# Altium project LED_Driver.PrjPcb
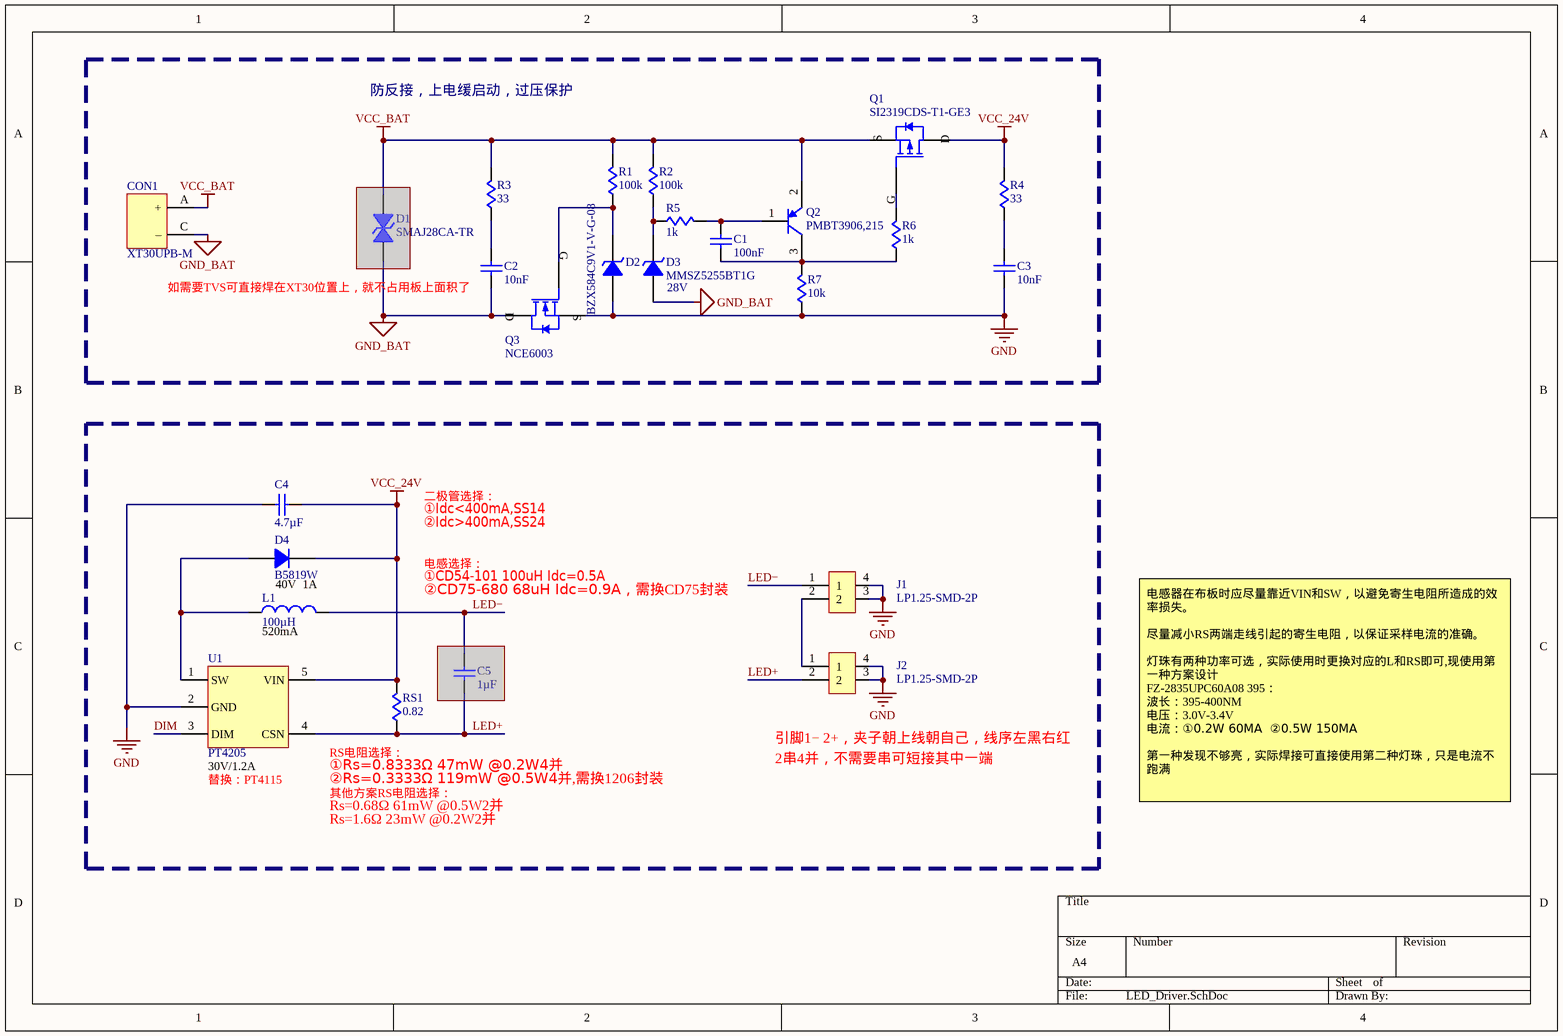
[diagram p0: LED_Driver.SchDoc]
1 sheet, 25 parts. Net scope: global (net labels, ports and power ports of the same name join across sheets).
Board file: LED_Driver.PcbDoc

## Sheet LED_Driver.SchDoc
size A4; SheetNumber: 1; SheetTotal: 1

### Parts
C1  value 100nF  [C 0603(1608)100_L]  (hidden comment: CL10B104KB8NNNC)
C2  value 10nF  [C 0603(1608)100_L]  (hidden comment: CL10B103KB8NNNC)
C3  value 10nF  [C 0603(1608)100_L]  (hidden comment: CL10B103KB8NNNC)
C4  value 4.7µF  [C 0805(2012)_L]  (hidden comment: CL21A475KBQNNNE)
C5  value 1µF  [C 0603(1608)100_L]  (hidden comment: CL10A105KB8NNNC)  (masked out: inside a compile mask, not in the netlist)
CON1  XT30UPB-M  [XT30UPB-M-内嵌（翻转）]
D1  SMAJ28CA-TR  [DO-214AC(SMA)-AA]  (masked out: inside a compile mask, not in the netlist)
D2  BZX584C9V1-V-G-08  [SOD-523]
D3  MMSZ5255BT1G  Voltage Rating (DC): 28V  [SOD-123]
D4  B5819W  Forward Current: 1A  Reverse Voltage (DC): 40V  [SOD-123]
J1  LP1.25-SMD-2P  [GH1.25-WS-2P]
J2  LP1.25-SMD-2P  [GH1.25-WS-2P]
L1  value 100µH  Current Rating: 520mA  [CD54]  (hidden comment: CD54NP-101KC)
Q1  SI2319CDS-T1-GE3  [SOT23-3L]
Q2  PMBT3906,215  [SOT23-3L]
Q3  NCE6003  [SOT23-3L]
R1  value 100k  [R 0603(1608)_L]  (hidden comment: RC0603FR-07100KL)
R2  value 100k  [R 0603(1608)_L]  (hidden comment: RC0603FR-07100KL)
R3  value 33  [R 0603(1608)_L]  (hidden comment: RC0603FR-0733RL)
R4  value 33  [R 0603(1608)_L]  (hidden comment: RC0603FR-0733RL)
R5  value 1k  [R 0603(1608)_L]  (hidden comment: RC0603FR-071KL)
R6  value 1k  [R 0603(1608)_L]  (hidden comment: RC0603FR-071KL)
R7  value 10k  [R 0603(1608)_L]  (hidden comment: RC0603FR-0710KL)
RS1  value 0.82  [R 0603(1608)_L]  (hidden comment: 0603WAF820LT5E)
U1  PT4205  [SOT89-5N]

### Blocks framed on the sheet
防反接，上电缓启动，过压保护: C1-C3 CON1 D1-D3 Q1-Q3 R1-R7

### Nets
GND: C3.1 C4.1 D2.1(A) J1.3 J1.4 J2.3 J2.4 Q3.2(SOURCE) R7.1 U1.2(GND)
GND_BAT: C2.1 CON1.C(–) D3.1(A) Q3.3(DRAIN)
VCC_24V: C4.2 D4.2(K) Q1.3(DRAIN) R4.2 RS1.2 U1.5(VIN)
VCC_BAT: CON1.A(+) Q1.2(SOURCE) Q2.2(E) R1.2 R2.2 R3.2
DIM: U1.3(DIM)
LED+: J2.2 RS1.1 U1.4(CSN)
LED−: J1.1 L1.2
NetC1_1: C1.1 Q2.3(C) R6.1 R7.2
NetC1_2: C1.2 Q2.1(B) R5.2
NetC2_2: C2.2 R3.1
NetC3_2: C3.2 R4.1
NetD2_2: D2.2(K) Q3.1(GATE) R1.1
NetD3_2: D3.2(K) R2.1 R5.1
NetD4_1: D4.1(A) L1.1 U1.1(SW)
NetJ1_2: J1.2 J2.1
NetQ1_1: Q1.1(GATE) R6.2

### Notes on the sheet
- 如需要TVS可直接焊在XT30位置上，就不占用板上面积了
- ①Idc<400mA,SS14
- 二极管选择：
- ①CD54-101 100uH Idc=0.5A
- ②Idc>400mA,SS24
- 电感选择：
- ②CD75-680 68uH Idc=0.9A，需换CD75封装
- (near U1) 30V/1.2A
- (near U1) 替换：PT4115
- ①Rs=0.8333Ω 47mW @0.2W4并
- ②Rs=0.3333Ω 119mW @0.5W4并,需换1206封装
- RS电阻选择：
- (near J2) 引脚1− 2+，夹子朝上线朝自己，线序左黑右红
- 2串4并，不需要串可短接其中一端
- Rs=0.68Ω 61mW @0.5W2并
- Rs=1.6Ω 23mW @0.2W2并
- 其他方案RS电阻选择：
- 电感器在布板时应尽量靠近VIN和SW，以避免寄生电阻所造成的效率损失。
  尽量减小RS两端走线引起的寄生电阻，以保证采样电流的准确。
  灯珠有两种功率可选，实际使用时更换对应的L和RS即可,现使用第一种方案设计
  FZ-2835UPC60A08 395：
  波长：395-400NM
  电压：3.0V-3.4V
  电流：①0.2W 60MA  ②0.5W 150MA
  第一种发现不够亮，实际焊接可直接使用第二种灯珠，只是电流不跑满

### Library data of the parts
C1 = CMP-001-00085-4: Multi Layer Ceramic Capacitor (MLCC) / Cap Ceramic 0.1uF 50V X7R 10% Pad SMD 0603 125¡ãC T/R
C2 C3 = CMP-001-00105-3: CAP CER 10000PF 50V X7R 0603; Material: Ceramic; Tolerance: 10%
C4 = CMP-001-00100-4: CAP CER 4.7UF 50V X5R 0805; Tolerance: 10%
C5 = CMP-001-00101-3: Ceramic capacitor SMD-0603 1000nF/50V X5R# K +-10%, Samsung, RoHS; Dielectric: X5R; Voltage Rating: 50V; Tolerance: 10%
CON1 = CMP-002-00073-11: 12.7x10.2mm 铜镀金 DC500V 15A; Momentary Current: 30A; Voltage Rating: 500V
D1 = CMP-004-00058-1: SMAJ Series 400 W 32.7 V Bi Directional Surface Mount TVS Diode - DO-214AC; Operating Supply Voltage: 28V; Clamping Voltage-Max: 59V; Test Current: 1mA; Power Dissipation: 400W; Element Configuration: Single; Max Reverse Leakage Current: 200nA; Reverse Breakdown Voltage: 31.1V; Max Breakdown Voltage: 32.7V; Value: 510pF; Peak Pulse Current: 39A; Number of Bidirectional Channels: 1; ESD Protection: Yes; Power Line Protection: No; Diode Type: ZENER
D2 = CMP-004-00055-5: Diode Zener Single 9.1V 5% 200mW 2-Pin SOD-523 T/R; Impedance: 15R; ESD Protection: No; Test Current: 5mA; Max Reverse Leakage Current: 500nA
D3 = CMP-004-00057-2: MMSZ5255BT1 Series 500 mW 10 mA 28 V SMT Zener Voltage Regulator - SOD-123; Max Reverse Current: 100nA; Voltage Tolerance: 5%; Power Rating: 500mW; Element Configuration: Single; Forward Voltage: 900mV; ESD Protection: Yes; Test Current: 4.5mA; Impedance: 44R; Material: Plastic; Zener Current: 10mA
D4 = CMP-004-00044-11: DIODE SCHOTTKY 20V 1A SOD123; Max Forward Surge Current (Ifsm): 10A; Forward Voltage: 550mV; Max Power Dissipation: 250mW; Element Configuration: Single; Max Reverse Current: 1mA
J1 J2 = CMP-002-00326-2: 脚距1.25，表面贴装，2pin接插件
L1 = CMP-006-00038-2: Ind Power Unshielded Wirewound 100uH 10% 1KHz 520mA Carrier T/R; Core Material: Ferrite; DC Resistance (DCR): 700mR
Q1 = CMP-013-00039-5: MOSFET P-CH 40V 4.4A SOT-23; Input Capacitance: 595pF; Polarity: P-CHANNEL; Turn-Off Delay Time: 20ns; Drain to Source Breakdown Voltage: -40V; Number of Channels: 1; Drain-source On Resistance-Max: 77mR; Element Configuration: Single; Continuous Drain Current (ID): -4.4A; Turn-On Delay Time: 40ns; Max Power Dissipation: 2.5W; Drain to Source Resistance: 64mR; Power Dissipation: 1.25W; Threshold Voltage: -1.2V; Gate to Source Voltage (Vgs): 20V
Q2 = CMP-013-00040-2: PNP Ic=-200mA Vceo=-40V hfe=100~300 fT=250MHz P=250mW; Power: 250mW
Q3 = MOS-00001-2: 60V 3A 1.7W 105m´Î@10V3A 2V@250Ã×A N Channel SOT-23(SOT-23-3) MOSFETs ROHS
R1 R2 = CMP-007-00090-4: RES SMD 100K OHM 1% 1/10W 0603; Working Voltage: 75V; Max Power Dissipation: 100mW; Voltage Rating: 50V; Temperature Coefficient: 100ppm/°C
R3 R4 = CMP-009-00202-4: Res Thick Film 0603 33 Ohm 1% 1/10W +/-100ppm/ßC Molded SMD Paper T/R; Power Rating: 100mW; Temperature Coefficient: 100ppm/°C; Voltage Rating (DC): 50V; Voltage Rating: 75V
R5 R6 = CMP-009-00199-4: Res Thick Film 0603 1K Ohm 1% 1/10W ±100ppm/°C Molded SMD SMD Paper T/R; Max Power Dissipation: 100mW; Voltage Rating: 50V
R7 = CMP-009-00017-13: RES SMD 10K OHM 1% 1/10W 0603; Voltage Rating: 75V; Max Power Dissipation: 100mW; Voltage Rating (DC): 50V; Temperature Coefficient: 100ppm/°C
RS1 = CMP-007-00091-3: 贴片电阻 0.82Ω ± 1.00% 0.1W ± 800ppm/℃ 0603; Tolerance: 1%; Power: 100mW
U1 = CMP-019-00087-5: 30V/1.2A/高调光比 LED 恒流驱动器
